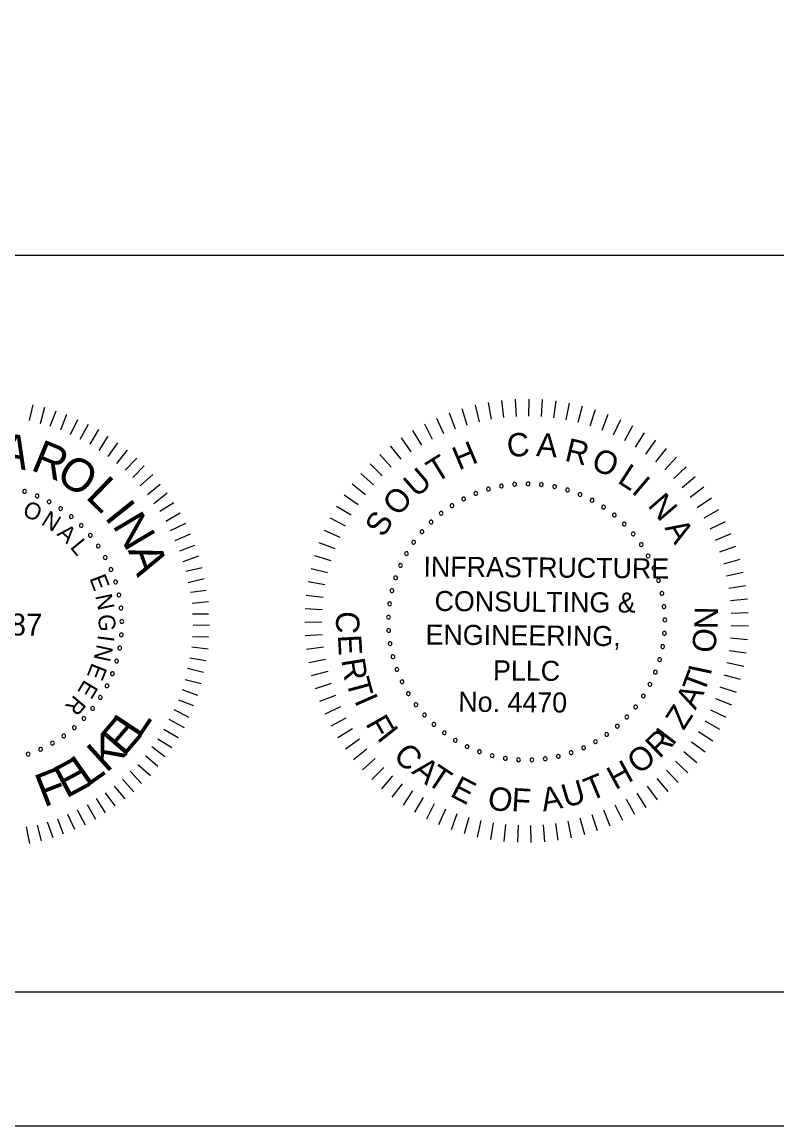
# Model space of a CAD drawing. Extents: x 1970675.2 to 1970711.3, y 796145.2 to 796167.2.
# Drawn here: x 1970699.687 to 1970702.503, y 796145.246 to 796149.367 of the extents above; entities that cross this region are included whole.
import ezdxf

# ---------------------------------------------------------------- set-up
doc = ezdxf.new("R2010")
doc.units = 0
for name, color, linetype in [('BR_BORDER LINES', 7, 'Continuous'), ('BR_TEXT', 7, 'Continuous'), ('Level 31', 7, 'Continuous')]:
    doc.layers.add(name, color=color, linetype=linetype)

msp = doc.modelspace()

# ---------------------------------------------------------------- linework, layer by layer
at = {"layer": 'BR_BORDER LINES'}
for p, q in [((1970697.8703, 796148.4964), (1970703.2355, 796148.4964)), ((1970677.0698, 796145.7463), (1970710.7358, 796145.7463))]:
    msp.add_line(p, q, dxfattribs=at)
at = {"layer": 'BR_TEXT'}
for p, q in [((1970701.5265, 796147.9587), (1970701.5298, 796147.8951)), ((1970701.5769, 796147.9597), (1970701.5764, 796147.8961)), ((1970701.6274, 796147.9577), (1970701.623, 796147.8942)), ((1970699.7143, 796147.8794), (1970699.7285, 796147.9385)), ((1970699.7554, 796147.8688), (1970699.7713, 796147.9295)), ((1970699.7922, 796147.8582), (1970699.8141, 796147.9155)), ((1970701.328, 796147.9239), (1970701.3466, 796147.863)), ((1970701.3767, 796147.9371), (1970701.3916, 796147.8752)), ((1970701.4262, 796147.9473), (1970701.4372, 796147.8846)), ((1970701.4761, 796147.9545), (1970701.4834, 796147.8913)), ((1970701.6776, 796147.9526), (1970701.6693, 796147.8895)), ((1970701.7274, 796147.9445), (1970701.7153, 796147.882)), ((1970701.7767, 796147.9333), (1970701.7608, 796147.8717)), ((1970701.8251, 796147.9192), (1970701.8055, 796147.8586)), ((1970699.8316, 796147.8449), (1970699.8535, 796147.9031)), ((1970699.8675, 796147.8275), (1970699.8954, 796147.883)), ((1970701.2334, 796147.8887), (1970701.2593, 796147.8305)), ((1970701.2802, 796147.9077), (1970701.3025, 796147.8481)), ((1970701.8726, 796147.9021), (1970701.8494, 796147.8428)), ((1970701.919, 796147.8822), (1970701.8922, 796147.8244)), ((1970699.9034, 796147.81), (1970699.9347, 796147.8656)), ((1970699.941, 796147.7917), (1970699.9732, 796147.8455)), ((1970701.1439, 796147.8422), (1970701.1766, 796147.7876)), ((1970701.1879, 796147.8668), (1970701.2173, 796147.8103)), ((1970701.9641, 796147.8594), (1970701.9338, 796147.8034)), ((1970702.0077, 796147.834), (1970701.974, 796147.78)), ((1970699.9743, 796147.7674), (1970700.0082, 796147.8212)), ((1970700.0075, 796147.7457), (1970700.044, 796147.796)), ((1970701.1014, 796147.8149), (1970701.1374, 796147.7625)), ((1970702.0497, 796147.8059), (1970702.0128, 796147.7541)), ((1970700.0399, 796147.7197), (1970700.0806, 796147.7691)), ((1970701.0217, 796147.7529), (1970701.0639, 796147.7052)), ((1970701.0606, 796147.7852), (1970701.0998, 796147.735)), ((1970702.0899, 796147.7754), (1970702.0499, 796147.7259)), ((1970700.0715, 796147.6945), (1970700.1147, 796147.7388)), ((1970700.0995, 796147.6668), (1970700.1428, 796147.7102)), ((1970700.9849, 796147.7184), (1970701.0299, 796147.6734)), ((1970702.1281, 796147.7424), (1970702.0852, 796147.6954)), ((1970700.1276, 796147.6357), (1970700.1752, 796147.6774)), ((1970700.9502, 796147.6817), (1970700.9979, 796147.6395)), ((1970702.1643, 796147.7072), (1970702.1186, 796147.6629)), ((1970702.1982, 796147.6699), (1970702.1499, 796147.6284)), ((1970700.1548, 796147.6037), (1970700.2015, 796147.6419)), ((1970700.9179, 796147.643), (1970700.968, 796147.6037)), ((1970702.2299, 796147.6305), (1970702.1791, 796147.5921)), ((1970700.1786, 796147.57), (1970700.2278, 796147.6091)), ((1970700.8879, 796147.6023), (1970700.9404, 796147.5662)), ((1970702.259, 796147.5893), (1970702.206, 796147.5541)), ((1970700.2006, 796147.5407), (1970700.2532, 796147.5729)), ((1970700.8605, 796147.5599), (1970700.9151, 796147.5271)), ((1970702.2856, 796147.5464), (1970702.2305, 796147.5145)), ((1970700.2226, 796147.5036), (1970700.2761, 796147.5349)), ((1970700.8358, 796147.5159), (1970700.8922, 796147.4865)), ((1970700.2404, 796147.4691), (1970700.2981, 796147.4961)), ((1970700.8137, 796147.4705), (1970700.8719, 796147.4445)), ((1970702.3095, 796147.5019), (1970702.2526, 796147.4734)), ((1970700.2581, 796147.4321), (1970700.315, 796147.4565)), ((1970700.7945, 796147.4238), (1970700.8541, 796147.4014)), ((1970702.3307, 796147.4561), (1970702.2722, 796147.4311)), ((1970700.2749, 796147.3933), (1970700.3318, 796147.4143)), ((1970702.3491, 796147.4091), (1970702.2891, 796147.3877)), ((1970700.2883, 796147.3529), (1970700.346, 796147.3747)), ((1970700.7782, 796147.3761), (1970700.839, 796147.3574)), ((1970702.3645, 796147.361), (1970702.3033, 796147.3433)), ((1970700.2984, 796147.3168), (1970700.3585, 796147.3308)), ((1970700.7648, 796147.3274), (1970700.8267, 796147.3124)), ((1970702.377, 796147.3121), (1970702.3148, 796147.2982)), ((1970700.3066, 796147.2746), (1970700.3668, 796147.2896)), ((1970700.7543, 796147.278), (1970700.817, 796147.2668)), ((1970702.3864, 796147.2625), (1970702.3236, 796147.2524)), ((1970700.3149, 796147.2385), (1970700.3741, 796147.2458)), ((1970700.747, 796147.228), (1970700.8102, 796147.2207)), ((1970700.3214, 796147.1973), (1970700.3824, 796147.2036)), ((1970700.7426, 796147.1777), (1970700.8062, 796147.1743)), ((1970702.3929, 796147.2124), (1970702.3295, 796147.2062)), ((1970700.3228, 796147.1578), (1970700.3829, 796147.1573)), ((1970702.3963, 796147.1621), (1970702.3326, 796147.1597)), ((1970700.325, 796147.1166), (1970700.3859, 796147.1161)), ((1970700.7414, 796147.1273), (1970700.8051, 796147.1277)), ((1970702.3965, 796147.1116), (1970702.3329, 796147.1131)), ((1970700.3221, 796147.0737), (1970700.3822, 796147.0715)), ((1970700.7432, 796147.0768), (1970700.8067, 796147.0812)), ((1970702.3938, 796147.0612), (1970702.3303, 796147.0666)), ((1970700.32, 796147.0351), (1970700.3809, 796147.0269)), ((1970700.7481, 796147.0266), (1970700.8113, 796147.0348)), ((1970702.3879, 796147.011), (1970702.3249, 796147.0203)), ((1970700.3129, 796146.994), (1970700.372, 796146.984)), ((1970700.7561, 796146.9767), (1970700.8186, 796146.9888)), ((1970702.379, 796146.9613), (1970702.3167, 796146.9744)), ((1970700.3039, 796146.9546), (1970700.3639, 796146.9403)), ((1970700.7671, 796146.9275), (1970700.8287, 796146.9433)), ((1970702.3671, 796146.9123), (1970702.3057, 796146.9291)), ((1970700.295, 796146.9126), (1970700.3549, 796146.8975)), ((1970700.781, 796146.8789), (1970700.8416, 796146.8985)), ((1970700.2844, 796146.8758), (1970700.3417, 796146.8538)), ((1970700.7979, 796146.8314), (1970700.8572, 796146.8546)), ((1970702.3522, 796146.864), (1970702.2919, 796146.8846)), ((1970700.2704, 796146.8373), (1970700.3268, 796146.8153)), ((1970700.8177, 796146.7849), (1970700.8755, 796146.8117)), ((1970702.3344, 796146.8168), (1970702.2755, 796146.841)), ((1970700.2346, 796146.7646), (1970700.2918, 796146.7341)), ((1970700.2529, 796146.8005), (1970700.3093, 796146.7726)), ((1970700.8403, 796146.7397), (1970700.8963, 796146.77)), ((1970702.3138, 796146.7707), (1970702.2564, 796146.7985)), ((1970700.2162, 796146.7279), (1970700.2692, 796146.6957)), ((1970700.8655, 796146.696), (1970700.9196, 796146.7297)), ((1970702.2904, 796146.726), (1970702.2348, 796146.7572)), ((1970700.1936, 796146.6911), (1970700.2457, 796146.659)), ((1970700.8934, 796146.654), (1970700.9453, 796146.6908)), ((1970702.2356, 796146.6412), (1970702.1843, 796146.6789)), ((1970702.2643, 796146.6828), (1970702.2107, 796146.7173)), ((1970700.1711, 796146.6622), (1970700.2197, 796146.6248)), ((1970700.9238, 796146.6137), (1970700.9734, 796146.6536)), ((1970702.2044, 796146.6015), (1970702.1555, 796146.6423)), ((1970700.1468, 796146.6289), (1970700.1928, 796146.589)), ((1970700.9566, 796146.5753), (1970701.0037, 796146.6182)), ((1970702.1709, 796146.5638), (1970702.1245, 796146.6074)), ((1970700.0905, 796146.5701), (1970700.133, 796146.5243)), ((1970700.119, 796146.5956), (1970700.1659, 796146.5541)), ((1970700.9917, 796146.539), (1970701.0361, 796146.5847)), ((1970702.1351, 796146.5281), (1970702.0915, 796146.5745)), ((1970700.03, 796146.5149), (1970700.0699, 796146.4673)), ((1970700.0619, 796146.5403), (1970700.1044, 796146.4936)), ((1970701.0289, 796146.5049), (1970701.0704, 796146.5532)), ((1970701.0682, 796146.4731), (1970701.1066, 796146.5239)), ((1970702.0574, 796146.4637), (1970702.0198, 796146.5151)), ((1970702.0973, 796146.4948), (1970702.0566, 796146.5437)), ((1970699.9972, 796146.4894), (1970700.0328, 796146.441)), ((1970701.1093, 796146.4438), (1970701.1446, 796146.4968)), ((1970702.0158, 796146.4352), (1970701.9813, 796146.4888)), ((1970699.9299, 796146.4462), (1970699.9612, 796146.3918)), ((1970699.9635, 796146.4682), (1970699.9966, 796146.4156)), ((1970701.1521, 796146.4171), (1970701.1841, 796146.4721)), ((1970701.1965, 796146.393), (1970701.225, 796146.4499)), ((1970701.9276, 796146.386), (1970701.9, 796146.4434)), ((1970701.9725, 796146.4093), (1970701.9414, 796146.4648)), ((1970699.8196, 796146.393), (1970699.8406, 796146.3362)), ((1970699.8558, 796146.4099), (1970699.8827, 796146.3539)), ((1970699.8919, 796146.4267), (1970699.9224, 796146.3707)), ((1970701.2422, 796146.3716), (1970701.2673, 796146.4302)), ((1970701.2892, 796146.3531), (1970701.3106, 796146.4131)), ((1970701.3372, 796146.3375), (1970701.3549, 796146.3986)), ((1970701.7859, 796146.3332), (1970701.7691, 796146.3947)), ((1970701.8342, 796146.3479), (1970701.8137, 796146.4082)), ((1970701.8815, 796146.3656), (1970701.8574, 796146.4245)), ((1970699.7018, 796146.3631), (1970699.715, 796146.3012)), ((1970699.743, 796146.3696), (1970699.758, 796146.3103)), ((1970699.78, 796146.3813), (1970699.801, 796146.3228)), ((1970701.386, 796146.3248), (1970701.4001, 796146.3869)), ((1970701.4356, 796146.3152), (1970701.4458, 796146.378)), ((1970701.4856, 796146.3086), (1970701.492, 796146.3719)), ((1970701.536, 796146.305), (1970701.5385, 796146.3686)), ((1970701.5865, 796146.3045), (1970701.5851, 796146.3682)), ((1970701.6369, 796146.3071), (1970701.6316, 796146.3706)), ((1970701.6871, 796146.3128), (1970701.6779, 796146.3758)), ((1970701.7368, 796146.3215), (1970701.7238, 796146.3838))]:
    msp.add_line(p, q, dxfattribs=at)
for centre, start, end in [((1970701.4268, 796147.6235), 16.1422, 196.1422), ((1970701.4753, 796147.635), 10.6038, 190.6038), ((1970701.4753, 796147.635), 190.6038, 10.6038), ((1970701.5247, 796147.6417), 5.0653, 185.0653), ((1970701.5247, 796147.6417), 185.0653, 5.0653), ((1970701.5745, 796147.6436), 359.5268, 179.5268), ((1970701.5745, 796147.6436), 179.5268, 359.5268), ((1970701.6242, 796147.6407), 173.9884, 353.9884), ((1970701.6242, 796147.6407), 353.9884, 173.9884), ((1970701.6735, 796147.6329), 168.4499, 348.4499), ((1970701.6735, 796147.6329), 348.4499, 168.4499), ((1970701.7217, 796147.6205), 342.9114, 162.9114), ((1970699.696, 796147.6149), 162.9114, 342.9114), ((1970699.696, 796147.6149), 342.9114, 162.9114), ((1970699.7429, 796147.5979), 157.373, 337.373), ((1970699.7429, 796147.5979), 337.373, 157.373), ((1970701.3343, 796147.587), 27.2191, 207.2191), ((1970701.3343, 796147.587), 207.2191, 27.2191), ((1970701.3797, 796147.6075), 21.6807, 201.6807), ((1970701.3797, 796147.6075), 201.6807, 21.6807), ((1970701.4268, 796147.6235), 196.1422, 16.1422), ((1970701.7217, 796147.6205), 162.9114, 342.9114), ((1970701.7686, 796147.6035), 157.373, 337.373), ((1970701.7686, 796147.6035), 337.373, 157.373), ((1970701.8135, 796147.582), 151.8345, 331.8345), ((1970701.8135, 796147.582), 331.8345, 151.8345), ((1970699.7878, 796147.5764), 151.8345, 331.8345), ((1970699.7878, 796147.5764), 331.8345, 151.8345), ((1970699.8305, 796147.5507), 146.2961, 326.2961), ((1970699.8305, 796147.5507), 326.2961, 146.2961), ((1970701.291, 796147.5621), 32.7576, 212.7576), ((1970701.291, 796147.5621), 212.7576, 32.7576), ((1970701.8562, 796147.5563), 146.2961, 326.2961), ((1970701.8562, 796147.5563), 326.2961, 146.2961), ((1970699.8705, 796147.521), 140.7576, 320.7576), ((1970699.8705, 796147.521), 320.7576, 140.7576), ((1970701.2128, 796147.5006), 43.8345, 223.8345), ((1970701.2128, 796147.5006), 223.8345, 43.8345), ((1970701.2504, 796147.5333), 38.2961, 218.2961), ((1970701.2504, 796147.5333), 218.2961, 38.2961), ((1970701.8962, 796147.5266), 140.7576, 320.7576), ((1970701.8962, 796147.5266), 320.7576, 140.7576), ((1970699.9075, 796147.4876), 135.2191, 315.2191), ((1970699.9075, 796147.4876), 315.2191, 135.2191), ((1970701.1785, 796147.4645), 49.373, 229.373), ((1970701.1785, 796147.4645), 229.373, 49.373), ((1970701.9332, 796147.4932), 135.2191, 315.2191), ((1970701.9332, 796147.4932), 315.2191, 135.2191), ((1970701.9668, 796147.4564), 129.6807, 309.6807), ((1970701.9668, 796147.4564), 309.6807, 129.6807), ((1970699.9411, 796147.4508), 129.6807, 309.6807), ((1970699.9411, 796147.4508), 309.6807, 129.6807), ((1970701.1478, 796147.4252), 54.9114, 234.9114), ((1970701.1478, 796147.4252), 234.9114, 54.9114), ((1970701.9966, 796147.4165), 124.1422, 304.1422), ((1970701.9966, 796147.4165), 304.1422, 124.1422), ((1970699.9709, 796147.4109), 124.1422, 304.1422), ((1970699.9709, 796147.4109), 304.1422, 124.1422), ((1970701.1211, 796147.3831), 60.4499, 240.4499), ((1970701.1211, 796147.3831), 240.4499, 60.4499), ((1970702.0225, 796147.3739), 118.6038, 298.6038), ((1970702.0225, 796147.3739), 298.6038, 118.6038), ((1970699.9968, 796147.3683), 118.6038, 298.6038), ((1970699.9968, 796147.3683), 298.6038, 118.6038), ((1970701.0986, 796147.3387), 65.9884, 245.9884), ((1970701.0986, 796147.3387), 245.9884, 65.9884), ((1970700.0184, 796147.3234), 113.0653, 293.0653), ((1970700.0184, 796147.3234), 293.0653, 113.0653), ((1970701.0804, 796147.2923), 71.5268, 251.5268), ((1970701.0804, 796147.2923), 251.5268, 71.5268), ((1970702.0441, 796147.329), 113.0653, 293.0653), ((1970702.0441, 796147.329), 293.0653, 113.0653), ((1970700.0356, 796147.2766), 107.5268, 287.5268), ((1970700.0356, 796147.2766), 287.5268, 107.5268), ((1970702.0613, 796147.2822), 107.5268, 287.5268), ((1970702.0613, 796147.2822), 287.5268, 107.5268), ((1970700.0482, 796147.2284), 101.9884, 281.9884), ((1970700.0482, 796147.2284), 281.9884, 101.9884), ((1970701.0668, 796147.2443), 77.0653, 257.0653), ((1970701.0668, 796147.2443), 257.0653, 77.0653), ((1970702.0739, 796147.234), 101.9884, 281.9884), ((1970702.0739, 796147.234), 281.9884, 101.9884), ((1970700.0561, 796147.1792), 96.4499, 276.4499), ((1970700.0561, 796147.1792), 276.4499, 96.4499), ((1970701.0579, 796147.1953), 82.6038, 262.6038), ((1970701.0579, 796147.1953), 262.6038, 82.6038), ((1970702.0818, 796147.1848), 96.4499, 276.4499), ((1970702.0818, 796147.1848), 276.4499, 96.4499), ((1970700.0592, 796147.1295), 90.9114, 270.9114), ((1970700.0592, 796147.1295), 270.9114, 90.9114), ((1970701.0538, 796147.1456), 88.1422, 268.1422), ((1970701.0538, 796147.1456), 268.1422, 88.1422), ((1970702.0849, 796147.1351), 90.9114, 270.9114), ((1970702.0849, 796147.1351), 270.9114, 90.9114), ((1970701.0545, 796147.0958), 93.6807, 273.6807), ((1970701.0545, 796147.0958), 273.6807, 93.6807), ((1970702.0832, 796147.0853), 85.373, 265.373), ((1970702.0832, 796147.0853), 265.373, 85.373), ((1970700.0575, 796147.0797), 85.373, 265.373), ((1970700.0575, 796147.0797), 265.373, 85.373), ((1970701.06, 796147.0463), 99.2191, 279.2191), ((1970701.06, 796147.0463), 279.2191, 99.2191), ((1970700.0509, 796147.0303), 79.8345, 259.8345), ((1970700.0509, 796147.0303), 259.8345, 79.8345), ((1970702.0766, 796147.0359), 79.8345, 259.8345), ((1970702.0766, 796147.0359), 259.8345, 79.8345), ((1970700.0397, 796146.9817), 74.2961, 254.2961), ((1970700.0397, 796146.9817), 254.2961, 74.2961), ((1970701.0703, 796146.9975), 104.7576, 284.7576), ((1970701.0703, 796146.9975), 284.7576, 104.7576), ((1970702.0654, 796146.9873), 74.2961, 254.2961), ((1970702.0654, 796146.9873), 254.2961, 74.2961), ((1970700.0238, 796146.9345), 68.7576, 248.7576), ((1970700.0238, 796146.9345), 248.7576, 68.7576), ((1970701.0852, 796146.95), 110.2961, 290.2961), ((1970701.0852, 796146.95), 290.2961, 110.2961), ((1970702.0495, 796146.9401), 68.7576, 248.7576), ((1970702.0495, 796146.9401), 248.7576, 68.7576), ((1970700.0034, 796146.889), 63.2191, 243.2191), ((1970700.0034, 796146.889), 243.2191, 63.2191), ((1970701.1046, 796146.9041), 115.8345, 295.8345), ((1970701.1046, 796146.9041), 295.8345, 115.8345), ((1970702.0291, 796146.8946), 63.2191, 243.2191), ((1970702.0291, 796146.8946), 243.2191, 63.2191), ((1970699.9788, 796146.8457), 57.6807, 237.6807), ((1970699.9788, 796146.8457), 237.6807, 57.6807), ((1970701.1284, 796146.8603), 121.373, 301.373), ((1970701.1284, 796146.8603), 301.373, 121.373), ((1970702.0045, 796146.8513), 57.6807, 237.6807), ((1970702.0045, 796146.8513), 237.6807, 57.6807), ((1970699.9501, 796146.805), 52.1422, 232.1422), ((1970699.9501, 796146.805), 232.1422, 52.1422), ((1970701.1563, 796146.819), 126.9114, 306.9114), ((1970701.1563, 796146.819), 306.9114, 126.9114), ((1970701.9758, 796146.8106), 52.1422, 232.1422), ((1970701.9758, 796146.8106), 232.1422, 52.1422), ((1970699.9175, 796146.7672), 46.6038, 226.6038), ((1970699.9175, 796146.7672), 226.6038, 46.6038), ((1970701.188, 796146.7806), 132.4499, 312.4499), ((1970701.188, 796146.7806), 312.4499, 132.4499), ((1970701.9432, 796146.7728), 46.6038, 226.6038), ((1970701.9432, 796146.7728), 226.6038, 46.6038), ((1970699.8815, 796146.7328), 41.0653, 221.0653), ((1970699.8815, 796146.7328), 221.0653, 41.0653), ((1970701.2233, 796146.7454), 137.9884, 317.9884), ((1970701.2233, 796146.7454), 317.9884, 137.9884), ((1970701.2618, 796146.7138), 323.5268, 143.5268), ((1970701.9072, 796146.7384), 41.0653, 221.0653), ((1970701.9072, 796146.7384), 221.0653, 41.0653), ((1970699.8004, 796146.6751), 29.9884, 209.9884), ((1970699.8423, 796146.702), 35.5268, 215.5268), ((1970699.8423, 796146.702), 215.5268, 35.5268), ((1970701.2618, 796146.7138), 143.5268, 323.5268), ((1970701.3032, 796146.6861), 149.0653, 329.0653), ((1970701.3032, 796146.6861), 329.0653, 149.0653), ((1970701.8261, 796146.6807), 29.9884, 209.9884), ((1970701.8261, 796146.6807), 209.9884, 29.9884), ((1970701.8681, 796146.7076), 35.5268, 215.5268), ((1970701.8681, 796146.7076), 215.5268, 35.5268), ((1970699.7097, 796146.6341), 18.9114, 198.9114), ((1970699.756, 796146.6524), 24.4499, 204.4499), ((1970699.756, 796146.6524), 204.4499, 24.4499), ((1970699.8004, 796146.6751), 209.9884, 29.9884), ((1970701.3471, 796146.6625), 154.6038, 334.6038), ((1970701.3471, 796146.6625), 334.6038, 154.6038), ((1970701.3931, 796146.6432), 160.1422, 340.1422), ((1970701.3931, 796146.6432), 340.1422, 160.1422), ((1970701.7354, 796146.6397), 18.9114, 198.9114), ((1970701.7354, 796146.6397), 198.9114, 18.9114), ((1970701.7817, 796146.658), 24.4499, 204.4499), ((1970701.7817, 796146.658), 204.4499, 24.4499), ((1970699.7097, 796146.6341), 198.9114, 18.9114), ((1970701.4407, 796146.6285), 165.6807, 345.6807), ((1970701.4407, 796146.6285), 345.6807, 165.6807), ((1970701.4895, 796146.6184), 171.2191, 351.2191), ((1970701.4895, 796146.6184), 351.2191, 171.2191), ((1970701.539, 796146.6131), 356.7576, 176.7576), ((1970701.539, 796146.6131), 176.7576, 356.7576), ((1970701.5889, 796146.6126), 2.2961, 182.2961), ((1970701.5889, 796146.6126), 182.2961, 2.2961), ((1970701.6385, 796146.6169), 7.8345, 187.8345), ((1970701.6385, 796146.6169), 187.8345, 7.8345), ((1970701.6875, 796146.6259), 13.373, 193.373), ((1970701.6875, 796146.6259), 193.373, 13.373)]:
    msp.add_arc(centre, 0.00701, start, end, dxfattribs=at)
at = {"layer": 'Level 31'}
msp.add_lwpolyline([(1970675.2365, 796145.2464), (1970711.2364, 796145.2464), (1970711.2364, 796167.2463), (1970675.2365, 796167.2463)], close=True, dxfattribs=at)

# ---------------------------------------------------------------- texts
at = {"layer": 'BR_TEXT'}
for s, height, rotation, p in [('C', 0.0872, 4.7281, (1970701.499, 796147.7421)), ('A', 0.1241, 348.1981, (1970699.5917, 796147.7163)), ('R', 0.1241, 337.4344, (1970699.715, 796147.6965)), ('H', 0.0872, 22.7882, (1970701.3162, 796147.6927)), ('A', 0.0872, 355.6981, (1970701.6035, 796147.7471)), ('R', 0.0872, 346.6681, (1970701.7077, 796147.7301)), ('T', 0.0872, 31.8182, (1970701.2313, 796147.6451)), ('O', 0.0872, 337.638, (1970701.8055, 796147.7003)), ('O', 0.1239, 326.5869, (1970699.8072, 796147.6597)), ('L', 0.0872, 327.108, (1970701.9043, 796147.6498)), ('L', 0.1241, 315.9488, (1970699.9198, 796147.5919)), ('U', 0.0872, 40.8482, (1970701.158, 796147.589)), ('I', 0.0872, 319.578, (1970701.9569, 796147.612)), ('O', 0.0872, 49.8782, (1970701.091, 796147.518)), ('N', 0.0872, 310.548, (1970702.0177, 796147.5612)), ('O', 0.0622, 338.4392, (1970699.6851, 796147.5247)), ('I', 0.1241, 308.6613, (1970699.9912, 796147.5176)), ('N', 0.0622, 328.2042, (1970699.7547, 796147.4933)), ('N', 0.1241, 300.7037, (1970700.0218, 796147.4883)), ('S', 0.0872, 58.9083, (1970701.0356, 796147.4398)), ('A', 0.0622, 318.657, (1970699.8137, 796147.4532)), ('A', 0.0872, 301.5179, (1970702.0828, 796147.4788)), ('L', 0.0622, 309.4546, (1970699.8635, 796147.4059)), ('A', 0.1241, 289.4792, (1970700.081, 796147.3952)), ('INFRASTRUCTURE', 0.074771, 359.5268, (1970701.1842, 796147.2972)), ('E', 0.0622, 291.049, (1970699.9373, 796147.2906)), ('N', 0.0622, 281.8466, (1970699.9595, 796147.2256)), ('CONSULTING &', 0.074771, 359.5268, (1970701.2255, 796147.1686)), ('N', 0.0872, 89.2085, (1970702.2821, 796147.1001)), ('No. 26987', 0.08175, 359.5268, (1970699.2574, 796147.0804)), ('G', 0.0622, 272.2995, (1970699.9713, 796147.1553)), ('C', 0.0872, 267.025, (1970700.8606, 796147.1698)), ('ENGINEERING,', 0.074771, 359.5268, (1970701.1919, 796147.0432)), ('O', 0.0872, 83.2085, (1970702.271, 796147.0086)), ('I', 0.0622, 262.4084, (1970699.9709, 796147.0814)), ('E', 0.0872, 273.025, (1970700.865, 796147.0783)), ('N', 0.0622, 257.7339, (1970699.9664, 796147.0468)), ('E', 0.0622, 248.1867, (1970699.9483, 796146.9779)), ('R', 0.0872, 279.025, (1970700.8778, 796146.986)), ('PLLC', 0.07477, 359.5268, (1970701.4436, 796146.9096)), ('T', 0.0872, 285.025, (1970700.8952, 796146.9072)), ('T', 0.0872, 69.3954, (1970702.2298, 796146.8568)), ('I', 0.0872, 77.9093, (1970702.2555, 796146.9243)), ('E', 0.0622, 238.9844, (1970699.9204, 796146.9151)), ('R', 0.0622, 229.782, (1970699.8827, 796146.8577)), ('I', 0.0872, 293.7713, (1970700.9249, 796146.8341)), ('No. 4470', 0.07477, 359.5268, (1970701.3141, 796146.7927)), ('A', 0.0872, 63.3954, (1970702.199, 796146.7965)), ('Z', 0.0872, 57.3954, (1970702.1551, 796146.7202)), ('E', 0.1236, 49.3639, (1970700.0662, 796146.6214)), ('L', 0.1236, 56.4247, (1970700.1237, 796146.6891)), ('F', 0.0872, 299.7713, (1970700.9661, 796146.748)), ('K', 0.1236, 42.3031, (1970700.0009, 796146.5613)), ('I', 0.0872, 308.5268, (1970701.0082, 796146.6942)), ('R', 0.0872, 44.5268, (1970702.0647, 796146.6152)), ('I', 0.0872, 52.3339, (1970702.1141, 796146.6625)), ('C', 0.0872, 314.5268, (1970701.0675, 796146.6241)), ('O', 0.0872, 38.5268, (1970701.9881, 796146.5552)), ('E', 0.1236, 28.1814, (1970699.8506, 796146.4673)), ('L', 0.1236, 35.2422, (1970699.9286, 796146.5097)), ('A', 0.0872, 320.5268, (1970701.1367, 796146.5655)), ('T', 0.0872, 326.5268, (1970701.1911, 796146.527)), ('H', 0.0872, 28.5268, (1970701.9, 796146.4992)), ('F', 0.1236, 21.1206, (1970699.7679, 796146.4348)), ('T', 0.0872, 22.5268, (1970701.8068, 796146.4575)), ('E', 0.0872, 332.5268, (1970701.2797, 796146.4792)), ('U', 0.0872, 16.5268, (1970701.7151, 796146.4331)), ('O', 0.0872, 350.5268, (1970701.4198, 796146.4304)), ('F', 0.0872, 356.5268, (1970701.5113, 796146.4212)), ('A', 0.0872, 10.5268, (1970701.6312, 796146.4196))]:
    msp.add_text(s, height=height, rotation=rotation, dxfattribs=at).set_placement(p)

doc.saveas('drawing.dxf')
